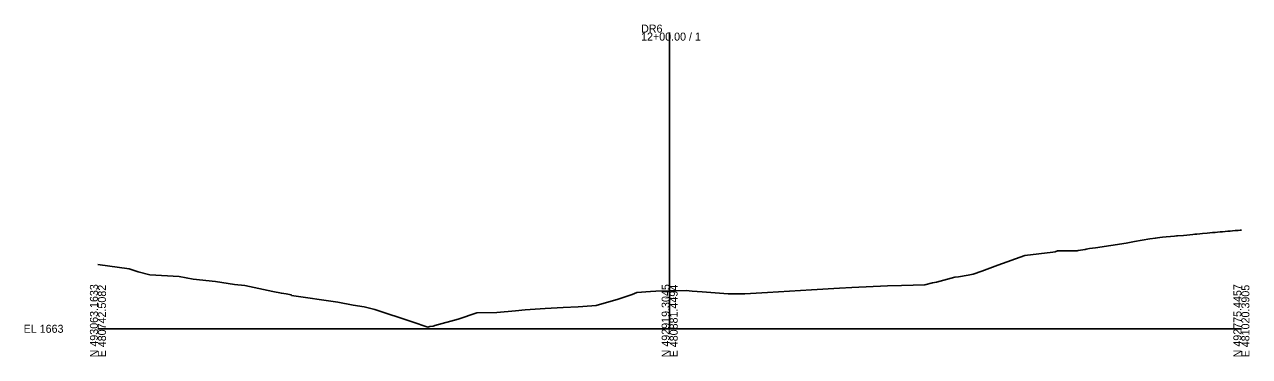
# Model space of a CAD drawing. Extents: x -26 to 403, y -88 to 5647.
# Drawn here: x -25.7 to 402.8, y 3990.3 to 4106.4 of the extents above; entities that cross this region are included whole.
import ezdxf

# ---------------------------------------------------------------- set-up
doc = ezdxf.new("R2010")
doc.units = 0
for name, color, linetype in [('Exist Cross Section Cell', 7, 'Continuous'), ('Exist XS Center Line Elevation Label', 7, 'Continuous'), ('Exist XS Ground Line', 7, 'Continuous')]:
    doc.layers.add(name, color=color, linetype=linetype)

msp = doc.modelspace()

# ---------------------------------------------------------------- linework, layer by layer
at = {"layer": 'Exist Cross Section Cell'}
for p, q in [((200, 4000), (200, 4103.6)), ((0, 4000), (200, 4000)), ((200, 4000), (400, 4000))]:
    msp.add_line(p, q, dxfattribs=at)
at = {"layer": 'Exist XS Ground Line'}
msp.add_lwpolyline([(0, 4022.52), (10.88, 4020.97), (14.12, 4019.91), (18.2, 4018.87), (28.44, 4018.29), (33.34, 4017.36), (41.07, 4016.5), (47.74, 4015.53), (51.43, 4015.13), (61.18, 4013.03), (64.19, 4012.46), (65.86, 4012.21), (67.61, 4011.85), (67.73, 4011.7), (83.97, 4009.31), (89.29, 4008.24), (93.13, 4007.63), (96.86, 4006.73), (109.92, 4002.47), (115.44, 4000.62), (116.11, 4000.82), (117.21, 4000.92), (117.56, 4001.07), (117.9, 4001.17), (125.99, 4003.37), (132.53, 4005.62), (139.57, 4005.66), (146.06, 4006.28), (149.42, 4006.61), (156.47, 4007.11), (162.77, 4007.5), (167.95, 4007.69), (172.82, 4008), (174.32, 4008.13), (181.95, 4010.39), (186.94, 4012.03), (188.55, 4012.75), (193.24, 4013.1), (195.22, 4013.18), (200, 4013.27), (201.28, 4013.29), (205.83, 4013.4), (207.89, 4013.21), (211.35, 4012.96), (220.52, 4012.19), (226.26, 4012.25), (234.17, 4012.68), (249.59, 4013.61), (259.36, 4014.18), (263.7, 4014.43), (276.26, 4015), (281.05, 4015.13), (289.22, 4015.4), (291.99, 4016.12), (293.29, 4016.36), (299.78, 4018.05), (300.99, 4018.18), (304.48, 4018.76), (306.14, 4019.15), (309.15, 4020.12), (314.8, 4022.21), (324.19, 4025.66), (334.06, 4026.82), (334.87, 4026.9), (335.66, 4027.26), (342.14, 4027.25), (342.56, 4027.32), (342.95, 4027.38), (345.3, 4027.79), (345.67, 4027.84), (346.92, 4028.03), (348.98, 4028.36), (359.67, 4030), (362.65, 4030.51), (367.98, 4031.42), (369.93, 4031.75), (370.67, 4031.83), (371.49, 4031.91), (372.36, 4032), (373.69, 4032.14), (375.2, 4032.28), (376.61, 4032.41), (377.25, 4032.47), (377.63, 4032.51), (379.73, 4032.69), (380.87, 4032.79), (381.94, 4032.9), (382.97, 4032.99), (383.76, 4033.06), (384.46, 4033.12), (385.48, 4033.21), (386.45, 4033.31), (388.07, 4033.45), (389, 4033.54), (389.93, 4033.63), (390.79, 4033.71), (391.66, 4033.79), (392.56, 4033.87), (393.42, 4033.94), (394.33, 4034.02), (395.26, 4034.1), (396.09, 4034.18), (396.89, 4034.25), (397.87, 4034.34), (398.86, 4034.43), (399.62, 4034.5), (400, 4034.53)], dxfattribs=at)

# ---------------------------------------------------------------- texts
at = {"layer": 'Exist Cross Section Cell'}
for s, p in [('DR6', (190, 4103.6)), ('12+00.00 / 1', (190, 4100.8)), ('EL 1663', (-26, 3998.6))]:
    msp.add_text(s, height=2.8, dxfattribs=at).set_placement(p)
for s, p in [('N 493063.1633', (0, 3990)), ('N 492919.3045', (200, 3990)), ('N 492775.4457', (400, 3990)), ('E 480742.5082', (2.8, 3990)), ('E 480881.4494', (202.8, 3990)), ('E 481020.3905', (402.8, 3990))]:
    msp.add_text(s, height=2.8, rotation=90, dxfattribs=at).set_placement(p)
at = {"layer": 'Exist XS Center Line Elevation Label'}
msp.add_text('1676.27', height=0.75, dxfattribs=at).set_placement((198.29, 4010.52))

doc.saveas('drawing.dxf')
